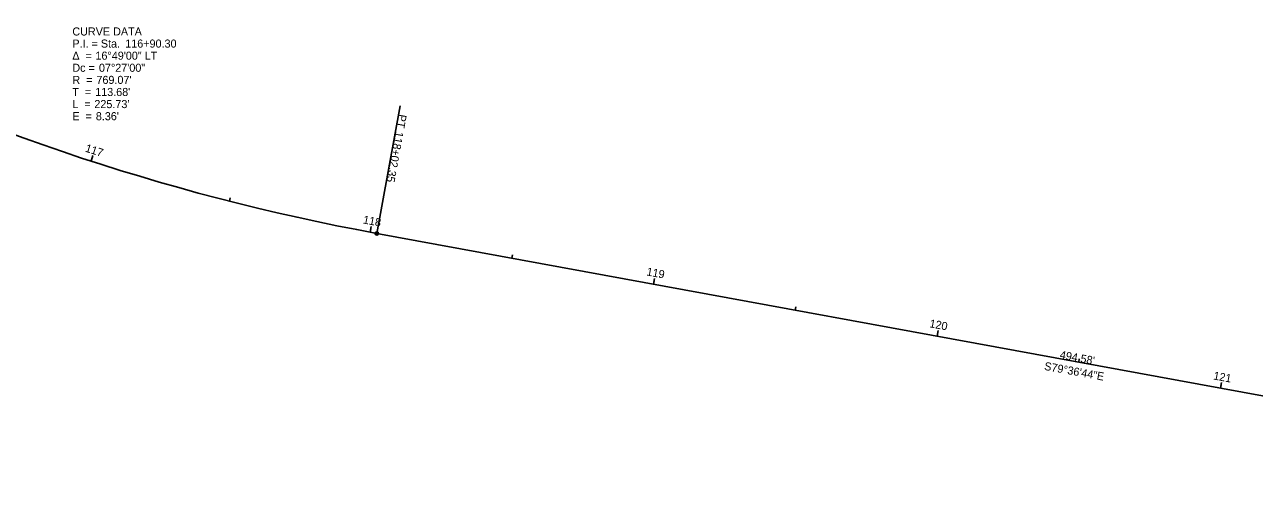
# Model space of a CAD drawing. Extents: x 2003596 to 2006888, y 572582 to 572983.
# Drawn here: x 2004422.8 to 2004849.6, y 572635.3 to 572797 of the extents above; entities that cross this region are included whole.
import ezdxf

# ---------------------------------------------------------------- set-up
doc = ezdxf.new("R2010")
doc.units = 0
for name, color, linetype in [('DR_X_Ditch', 7, 'Continuous'), ('DR_X_Headwall', 7, 'Continuous'), ('PM_X_CL_Double_Solid', 7, 'Continuous'), ('PM_X_Edge_Line', 7, 'Continuous'), ('PM_X_Surveyed_Line', 7, 'Continuous'), ('PV_X_COP', 7, 'Continuous'), ('PV_X_EOP', 7, 'Continuous'), ('RD_X_Fence', 7, 'Continuous'), ('SV_X_Break_Lines', 7, 'Continuous'), ('SV_X_Top_of_Bank', 7, 'Continuous'), ('UT_X_Water', 7, 'Continuous'), ('UT_X_Water_Cells', 7, 'Continuous'), ('VG_X_Tree_Line_Lt', 7, 'Continuous'), ('XS_X_Ground_Line', 7, 'Continuous')]:
    doc.layers.add(name, color=color, linetype=linetype)

msp = doc.modelspace()

# ---------------------------------------------------------------- linework, layer by layer
at = {"layer": 'DR_X_Ditch'}
for p, q in [((2004445.86, 572749.59), (2004446.48, 572751.49)), ((2004493.88, 572735.68), (2004494.17, 572736.85)), ((2004542.7, 572724.92), (2004543.06, 572726.89)), ((2004591.88, 572715.91), (2004592.09, 572717.09)), ((2004641.06, 572706.89), (2004641.42, 572708.86)), ((2004690.24, 572697.87), (2004690.45, 572699.05)), ((2004739.42, 572688.86), (2004739.78, 572690.83)), ((2004788.6, 572679.84), (2004788.81, 572681.02)), ((2004837.78, 572670.83), (2004838.14, 572672.79))]:
    msp.add_line(p, q, dxfattribs=at)
at = {"layer": 'PM_X_Surveyed_Line'}
msp.add_line((2004545, 572724.5), (2005031.48, 572635.32), dxfattribs=at)
msp.add_arc((2004683.7, 573480.96), 769.07, 242.79359, 259.61026, dxfattribs=at)
at = {"layer": 'PV_X_COP'}
msp.add_line((2004545, 572724.5), (2004553.12, 572768.76), dxfattribs=at)
msp.add_circle((2004545, 572724.5), 0.6, dxfattribs=at)
at = {"layer": 'RD_X_Fence'}
for p, q in [((2004445.86, 572749.59), (2004446.23, 572750.73)), ((2004542.7, 572724.92), (2004542.92, 572726.1)), ((2004641.06, 572706.89), (2004641.27, 572708.07)), ((2004739.42, 572688.86), (2004739.78, 572690.83)), ((2004837.78, 572670.83), (2004837.99, 572672.01))]:
    msp.add_line(p, q, dxfattribs=at)
at = {"layer": 'SV_X_Top_of_Bank'}
msp.add_line((2004545, 572724.5), (2004553.12, 572768.76), dxfattribs=at)
msp.add_circle((2004545, 572724.5), 0.6, dxfattribs=at)
at = {"layer": 'UT_X_Water_Cells'}
msp.add_line((2004739.42, 572688.86), (2004739.78, 572690.83), dxfattribs=at)
at = {"layer": 'VG_X_Tree_Line_Lt'}
msp.add_line((2004545, 572724.5), (2004553.12, 572768.76), dxfattribs=at)
msp.add_circle((2004545, 572724.5), 0.6, dxfattribs=at)

# ---------------------------------------------------------------- texts
at = {"layer": 'DR_X_Ditch'}
for s, rotation, p in [('117', 341.9854, (2004443.59, 572752.95)), ('118', 349.4354, (2004540.08, 572728)), ('119', 349.6122, (2004638.46, 572709.96)), ('120', 349.6122, (2004736.65, 572691.96)), ('121', 349.6122, (2004835.17, 572673.85))]:
    msp.add_text(s, height=2.8, rotation=rotation, dxfattribs=at).set_placement(p)
at = {"layer": 'DR_X_Headwall'}
for s, p in [('CURVE DATA', (2004439.35, 572793.19)), ('P.I. = Sta. ', (2004439.35, 572788.99)), ('116+90.30', (2004457.71, 572788.99)), ('Δ  = ', (2004439.35, 572784.79)), ('16°49\'00" LT', (2004447.37, 572784.79)), ('Dc = ', (2004439.35, 572780.59)), ('07°27\'00"', (2004448.58, 572780.59)), ('R  = ', (2004439.35, 572776.39)), ("769.07'", (2004447.71, 572776.39)), ('T  = ', (2004439.35, 572772.19)), ("113.68'", (2004447.28, 572772.19)), ('L  = ', (2004439.35, 572767.99)), ("225.73'", (2004446.99, 572767.99)), ('E  = ', (2004439.35, 572763.79)), ("8.36'", (2004447.5, 572763.79))]:
    msp.add_text(s, height=2.8, dxfattribs=at).set_placement(p)
at = {"layer": 'PM_X_CL_Double_Solid'}
msp.add_text("494.58'", height=2.8, rotation=349.6122, dxfattribs=at).set_placement((2004781.87, 572681.12))
at = {"layer": 'PM_X_Edge_Line'}
msp.add_text("494.58'", height=2.8, rotation=349.6122, dxfattribs=at).set_placement((2004781.87, 572681.12))
at = {"layer": 'PV_X_COP'}
for s, p in [('PT', (2004552.66, 572766.02)), ('118+02.35', (2004551.57, 572760.04))]:
    msp.add_text(s, height=2.8, rotation=259.6122, dxfattribs=at).set_placement(p)
at = {"layer": 'PV_X_EOP'}
msp.add_text('S79°36\'44"E', height=2.8, rotation=349.6122, dxfattribs=at).set_placement((2004776.48, 572677.18))
at = {"layer": 'RD_X_Fence'}
msp.add_text('120', height=2.8, rotation=349.6122, dxfattribs=at).set_placement((2004736.65, 572691.96))
at = {"layer": 'SV_X_Break_Lines'}
msp.add_text('S79°36\'44"E', height=2.8, rotation=349.6122, dxfattribs=at).set_placement((2004776.48, 572677.18))
at = {"layer": 'SV_X_Top_of_Bank'}
for s, p in [('PT', (2004552.66, 572766.02)), ('118+02.35', (2004551.57, 572760.04))]:
    msp.add_text(s, height=2.8, rotation=259.6122, dxfattribs=at).set_placement(p)
at = {"layer": 'UT_X_Water'}
msp.add_text('S79°36\'44"E', height=2.8, rotation=349.6122, dxfattribs=at).set_placement((2004776.48, 572677.18))
at = {"layer": 'UT_X_Water_Cells'}
msp.add_text('120', height=2.8, rotation=349.6122, dxfattribs=at).set_placement((2004736.65, 572691.96))
at = {"layer": 'VG_X_Tree_Line_Lt'}
for s, p in [('PT', (2004552.66, 572766.02)), ('118+02.35', (2004551.57, 572760.04))]:
    msp.add_text(s, height=2.8, rotation=259.6122, dxfattribs=at).set_placement(p)
at = {"layer": 'XS_X_Ground_Line'}
msp.add_text("494.58'", height=2.8, rotation=349.6122, dxfattribs=at).set_placement((2004781.87, 572681.12))

doc.saveas('drawing.dxf')
